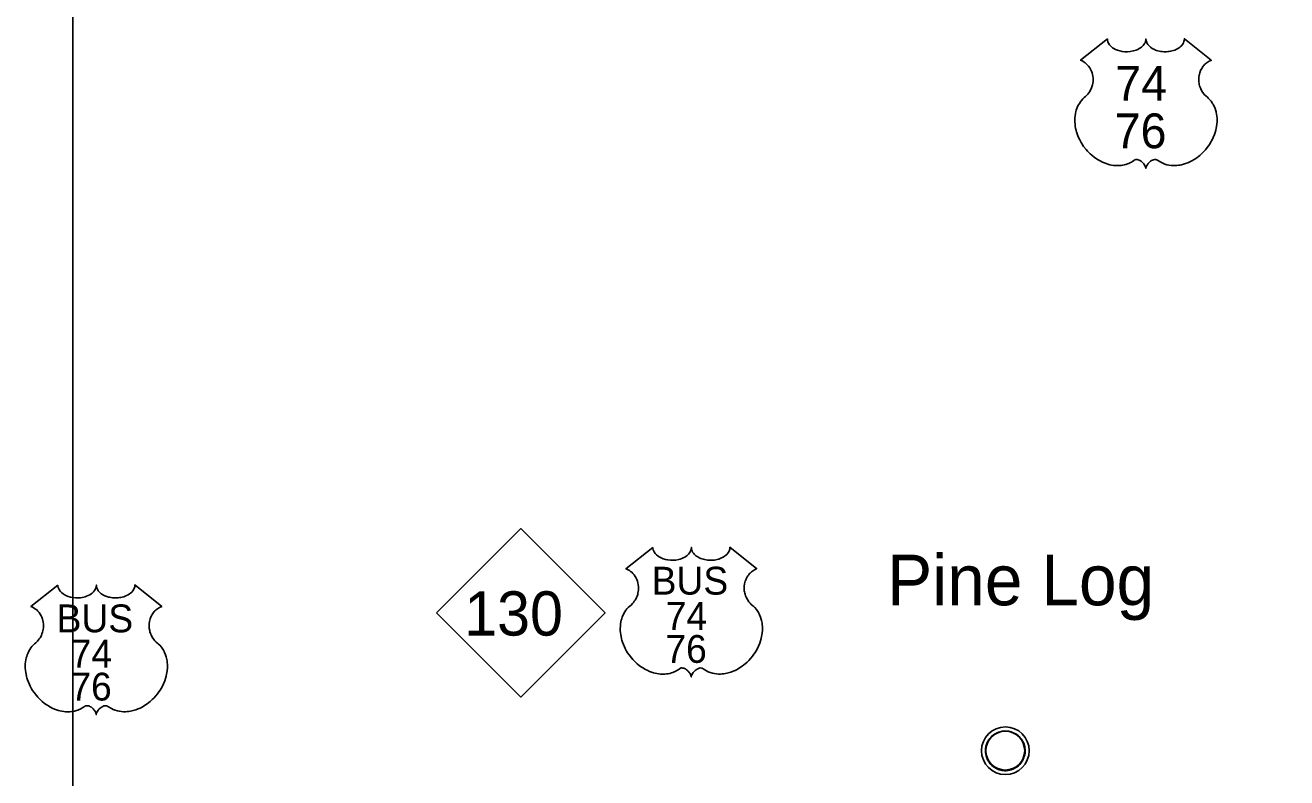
# Model space of a CAD drawing. Extents: x 5197761 to 5514561, y 1890130 to 2080942.
# Drawn here: x 5298153 to 5318095, y 2009899 to 2021798 of the extents above; entities that cross this region are included whole.
import ezdxf

# ---------------------------------------------------------------- set-up
doc = ezdxf.new("R2010")
doc.units = 0
for name, color, linetype in [('Exist Civil Demographics Community CELL', 7, 'Continuous'), ('Exist Civil Demographics Community Label', 7, 'Continuous'), ('Exist Road Primary NC Shield CELL', 7, 'Continuous'), ('Exist Road Primary NC Shield Number Label', 7, 'Continuous'), ('Exist Road Primary US Shield CELL', 7, 'Continuous'), ('Exist Road Primary US Shield Number Label', 7, 'Continuous'), ('Map Preparation Inset Cut Line', 7, 'Continuous')]:
    doc.layers.add(name, color=color, linetype=linetype)

msp = doc.modelspace()

# ---------------------------------------------------------------- linework, layer by layer
at = {"layer": 'Exist Civil Demographics Community CELL'}
msp.add_lwpolyline([(5313336, 2010377), (5313340, 2010399), (5313347, 2010426), (5313359, 2010454), (5313370, 2010477), (5313384, 2010500), (5313399, 2010521), (5313415, 2010538), (5313433, 2010557), (5313455, 2010575), (5313477, 2010590), (5313496, 2010601), (5313517, 2010611), (5313538, 2010620), (5313561, 2010627), (5313578, 2010632), (5313598, 2010635), (5313614, 2010638), (5313640, 2010639), (5313657, 2010638), (5313680, 2010637), (5313700, 2010635), (5313719, 2010631), (5313739, 2010625), (5313760, 2010617), (5313787, 2010606), (5313812, 2010592), (5313832, 2010577), (5313853, 2010561), (5313866, 2010549), (5313882, 2010531), (5313898, 2010512), (5313910, 2010494), (5313923, 2010474), (5313932, 2010453), (5313941, 2010433), (5313947, 2010413), (5313952, 2010395), (5313956, 2010371), (5313959, 2010352), (5313960, 2010328), (5313959, 2010305), (5313957, 2010282), (5313953, 2010260), (5313946, 2010235), (5313939, 2010212), (5313930, 2010192), (5313917, 2010168), (5313904, 2010147), (5313890, 2010128), (5313873, 2010109), (5313852, 2010089), (5313832, 2010072), (5313812, 2010059), (5313795, 2010049), (5313767, 2010036), (5313739, 2010025), (5313715, 2010019), (5313689, 2010014), (5313671, 2010012), (5313653, 2010011), (5313631, 2010011), (5313614, 2010013), (5313591, 2010015), (5313567, 2010021), (5313549, 2010026), (5313528, 2010033), (5313510, 2010041), (5313494, 2010050), (5313467, 2010067), (5313445, 2010084), (5313425, 2010102), (5313407, 2010121), (5313395, 2010137), (5313383, 2010154), (5313366, 2010182), (5313359, 2010196), (5313352, 2010212), (5313342, 2010245), (5313336, 2010273), (5313333, 2010294), (5313332, 2010319), (5313332, 2010338), (5313334, 2010364)], close=True, dxfattribs=at)
for centre, radius in [((5313646, 2010327), 377), ((5313645, 2010328), 307)]:
    msp.add_circle(centre, radius, dxfattribs=at)
at = {"layer": 'Exist Road Primary NC Shield CELL'}
msp.add_lwpolyline([(5304655, 2012506), (5305987, 2013838), (5307319, 2012506), (5305987, 2011174)], close=True, dxfattribs=at)
at = {"layer": 'Exist Road Primary US Shield CELL'}
for points in [[(5315260, 2021581), (5315261, 2021564), (5315265, 2021543), (5315268, 2021532), (5315278, 2021512), (5315294, 2021487), (5315317, 2021463), (5315342, 2021443), (5315359, 2021431), (5315388, 2021416), (5315421, 2021402), (5315458, 2021392), (5315495, 2021384), (5315536, 2021379), (5315577, 2021379), (5315620, 2021382), (5315668, 2021391), (5315691, 2021397), (5315716, 2021406), (5315739, 2021415), (5315764, 2021429), (5315784, 2021442), (5315800, 2021453), (5315823, 2021475), (5315841, 2021497), (5315848, 2021510), (5315855, 2021522), (5315864, 2021548), (5315866, 2021559), (5315868, 2021582), (5315870, 2021563), (5315872, 2021550), (5315875, 2021538), (5315880, 2021525), (5315889, 2021507), (5315899, 2021492), (5315918, 2021470), (5315930, 2021459), (5315941, 2021450), (5315969, 2021430), (5316003, 2021413), (5316020, 2021406), (5316037, 2021400), (5316058, 2021393), (5316081, 2021388), (5316103, 2021384), (5316125, 2021381), (5316149, 2021379), (5316167, 2021379), (5316191, 2021379), (5316212, 2021380), (5316234, 2021383), (5316258, 2021387), (5316277, 2021391), (5316303, 2021398), (5316326, 2021406), (5316346, 2021415), (5316373, 2021429), (5316394, 2021442), (5316409, 2021455), (5316428, 2021472), (5316446, 2021492), (5316456, 2021507), (5316463, 2021522), (5316470, 2021538), (5316474, 2021555), (5316476, 2021570), (5316477, 2021583), (5316902, 2021244), (5316892, 2021240), (5316869, 2021229), (5316850, 2021218), (5316821, 2021198), (5316808, 2021186), (5316796, 2021175), (5316784, 2021162), (5316774, 2021150), (5316762, 2021133), (5316751, 2021116), (5316740, 2021097), (5316732, 2021081), (5316719, 2021047), (5316713, 2021025), (5316709, 2021007), (5316704, 2020969), (5316702, 2020951), (5316702, 2020933), (5316703, 2020914), (5316705, 2020896), (5316708, 2020877), (5316711, 2020861), (5316717, 2020840), (5316724, 2020817), (5316734, 2020794), (5316753, 2020757), (5316778, 2020719), (5316796, 2020698), (5316813, 2020680), (5316840, 2020658), (5316854, 2020645), (5316870, 2020629), (5316897, 2020598), (5316908, 2020583), (5316918, 2020567), (5316929, 2020550), (5316939, 2020532), (5316947, 2020516), (5316962, 2020480), (5316972, 2020445), (5316977, 2020426), (5316985, 2020384), (5316988, 2020364), (5316992, 2020323), (5316992, 2020274), (5316988, 2020227), (5316979, 2020172), (5316972, 2020140), (5316961, 2020102), (5316950, 2020069), (5316931, 2020021), (5316913, 2019985), (5316891, 2019944), (5316876, 2019919), (5316858, 2019893), (5316835, 2019862), (5316809, 2019829), (5316778, 2019795), (5316753, 2019770), (5316720, 2019740), (5316699, 2019723), (5316671, 2019702), (5316632, 2019676), (5316593, 2019653), (5316560, 2019636), (5316531, 2019624), (5316493, 2019610), (5316431, 2019592), (5316408, 2019587), (5316381, 2019583), (5316355, 2019581), (5316331, 2019579), (5316297, 2019579), (5316265, 2019582), (5316233, 2019586), (5316201, 2019593), (5316167, 2019603), (5316136, 2019615), (5316105, 2019631), (5316053, 2019664), (5316037, 2019672), (5316029, 2019674), (5316009, 2019675), (5315990, 2019671), (5315970, 2019663), (5315958, 2019657), (5315942, 2019647), (5315930, 2019637), (5315916, 2019623), (5315906, 2019612), (5315898, 2019603), (5315883, 2019579), (5315878, 2019568), (5315873, 2019554), (5315868, 2019533), (5315861, 2019560), (5315853, 2019577), (5315844, 2019592), (5315835, 2019606), (5315820, 2019623), (5315807, 2019635), (5315791, 2019648), (5315773, 2019659), (5315760, 2019666), (5315747, 2019671), (5315732, 2019674), (5315719, 2019675), (5315709, 2019675), (5315695, 2019672), (5315676, 2019658), (5315657, 2019645), (5315638, 2019633), (5315614, 2019621), (5315597, 2019613), (5315576, 2019605), (5315552, 2019596), (5315526, 2019590), (5315499, 2019584), (5315475, 2019581), (5315450, 2019578), (5315427, 2019578), (5315403, 2019578), (5315381, 2019580), (5315355, 2019582), (5315323, 2019587), (5315296, 2019593), (5315268, 2019600), (5315239, 2019609), (5315209, 2019621), (5315170, 2019638), (5315143, 2019652), (5315101, 2019676), (5315051, 2019711), (5315013, 2019741), (5314986, 2019766), (5314945, 2019807), (5314922, 2019834), (5314884, 2019882), (5314861, 2019917), (5314845, 2019943), (5314823, 2019984), (5314810, 2020010), (5314794, 2020047), (5314781, 2020082), (5314771, 2020114), (5314765, 2020135), (5314757, 2020172), (5314752, 2020198), (5314748, 2020233), (5314745, 2020270), (5314744, 2020305), (5314745, 2020334), (5314749, 2020367), (5314754, 2020402), (5314761, 2020433), (5314767, 2020455), (5314776, 2020481), (5314788, 2020511), (5314802, 2020539), (5314816, 2020562), (5314832, 2020587), (5314849, 2020609), (5314871, 2020632), (5314893, 2020654), (5314914, 2020671), (5314939, 2020695), (5314951, 2020709), (5314967, 2020730), (5314979, 2020748), (5314989, 2020765), (5315002, 2020790), (5315010, 2020809), (5315019, 2020837), (5315024, 2020857), (5315029, 2020883), (5315033, 2020908), (5315034, 2020938), (5315033, 2020963), (5315030, 2020993), (5315024, 2021021), (5315018, 2021045), (5315007, 2021074), (5314997, 2021094), (5314981, 2021122), (5314963, 2021148), (5314944, 2021169), (5314926, 2021188), (5314907, 2021202), (5314890, 2021214), (5314869, 2021227), (5314848, 2021238), (5314835, 2021243)], [(5308074, 2013541), (5308075, 2013524), (5308080, 2013503), (5308083, 2013492), (5308093, 2013471), (5308109, 2013447), (5308131, 2013423), (5308157, 2013402), (5308174, 2013391), (5308203, 2013376), (5308236, 2013362), (5308272, 2013351), (5308310, 2013344), (5308351, 2013339), (5308391, 2013338), (5308435, 2013342), (5308483, 2013351), (5308505, 2013357), (5308530, 2013365), (5308553, 2013375), (5308579, 2013388), (5308599, 2013402), (5308615, 2013413), (5308637, 2013435), (5308655, 2013457), (5308663, 2013470), (5308669, 2013482), (5308678, 2013507), (5308681, 2013519), (5308683, 2013542), (5308684, 2013522), (5308686, 2013510), (5308689, 2013498), (5308694, 2013485), (5308703, 2013467), (5308714, 2013452), (5308732, 2013430), (5308744, 2013419), (5308755, 2013410), (5308784, 2013390), (5308818, 2013373), (5308834, 2013366), (5308851, 2013360), (5308873, 2013353), (5308895, 2013348), (5308917, 2013344), (5308940, 2013341), (5308963, 2013339), (5308982, 2013338), (5309005, 2013339), (5309026, 2013340), (5309048, 2013342), (5309072, 2013346), (5309092, 2013351), (5309117, 2013358), (5309140, 2013366), (5309161, 2013375), (5309187, 2013388), (5309208, 2013402), (5309224, 2013414), (5309243, 2013431), (5309260, 2013452), (5309270, 2013467), (5309278, 2013482), (5309284, 2013498), (5309289, 2013515), (5309291, 2013530), (5309291, 2013543), (5309716, 2013204), (5309706, 2013200), (5309683, 2013189), (5309665, 2013178), (5309635, 2013157), (5309623, 2013146), (5309610, 2013134), (5309599, 2013122), (5309589, 2013110), (5309576, 2013093), (5309565, 2013076), (5309554, 2013057), (5309547, 2013041), (5309534, 2013006), (5309527, 2012985), (5309523, 2012966), (5309518, 2012928), (5309517, 2012910), (5309517, 2012893), (5309518, 2012874), (5309520, 2012856), (5309523, 2012837), (5309526, 2012820), (5309531, 2012800), (5309539, 2012776), (5309548, 2012753), (5309568, 2012716), (5309593, 2012679), (5309610, 2012658), (5309628, 2012640), (5309654, 2012618), (5309668, 2012605), (5309685, 2012589), (5309711, 2012558), (5309722, 2012543), (5309733, 2012527), (5309743, 2012510), (5309753, 2012492), (5309761, 2012476), (5309776, 2012440), (5309787, 2012404), (5309792, 2012386), (5309800, 2012344), (5309803, 2012323), (5309806, 2012283), (5309806, 2012233), (5309803, 2012187), (5309794, 2012132), (5309786, 2012100), (5309775, 2012062), (5309764, 2012029), (5309745, 2011980), (5309728, 2011945), (5309706, 2011904), (5309690, 2011879), (5309672, 2011852), (5309650, 2011822), (5309624, 2011789), (5309593, 2011755), (5309567, 2011729), (5309534, 2011700), (5309514, 2011683), (5309485, 2011661), (5309446, 2011635), (5309407, 2011613), (5309375, 2011596), (5309345, 2011584), (5309308, 2011569), (5309245, 2011552), (5309222, 2011547), (5309195, 2011543), (5309170, 2011541), (5309145, 2011539), (5309112, 2011539), (5309079, 2011542), (5309048, 2011546), (5309016, 2011553), (5308982, 2011563), (5308951, 2011575), (5308920, 2011590), (5308867, 2011624), (5308852, 2011632), (5308843, 2011634), (5308823, 2011635), (5308804, 2011631), (5308784, 2011623), (5308773, 2011617), (5308757, 2011606), (5308745, 2011597), (5308730, 2011583), (5308720, 2011572), (5308713, 2011562), (5308698, 2011539), (5308693, 2011528), (5308687, 2011514), (5308682, 2011493), (5308676, 2011519), (5308668, 2011537), (5308659, 2011552), (5308649, 2011565), (5308634, 2011582), (5308621, 2011595), (5308605, 2011608), (5308588, 2011619), (5308574, 2011626), (5308562, 2011630), (5308546, 2011634), (5308534, 2011635), (5308524, 2011635), (5308509, 2011632), (5308490, 2011618), (5308472, 2011605), (5308452, 2011593), (5308429, 2011580), (5308411, 2011572), (5308391, 2011564), (5308367, 2011556), (5308340, 2011549), (5308314, 2011544), (5308290, 2011540), (5308265, 2011538), (5308242, 2011537), (5308218, 2011538), (5308196, 2011539), (5308170, 2011542), (5308138, 2011546), (5308111, 2011552), (5308083, 2011560), (5308054, 2011569), (5308023, 2011581), (5307984, 2011598), (5307958, 2011611), (5307915, 2011636), (5307865, 2011670), (5307828, 2011701), (5307800, 2011726), (5307760, 2011767), (5307736, 2011794), (5307699, 2011842), (5307675, 2011877), (5307660, 2011902), (5307637, 2011944), (5307625, 2011969), (5307609, 2012007), (5307596, 2012042), (5307585, 2012074), (5307580, 2012095), (5307572, 2012131), (5307567, 2012157), (5307562, 2012193), (5307559, 2012230), (5307559, 2012265), (5307560, 2012293), (5307563, 2012327), (5307569, 2012362), (5307575, 2012392), (5307582, 2012414), (5307591, 2012441), (5307603, 2012470), (5307617, 2012498), (5307630, 2012522), (5307647, 2012547), (5307663, 2012568), (5307685, 2012592), (5307708, 2012613), (5307729, 2012630), (5307753, 2012654), (5307766, 2012669), (5307781, 2012689), (5307794, 2012708), (5307803, 2012725), (5307816, 2012750), (5307824, 2012768), (5307834, 2012797), (5307839, 2012817), (5307844, 2012843), (5307847, 2012867), (5307848, 2012898), (5307848, 2012923), (5307844, 2012952), (5307839, 2012980), (5307832, 2013005), (5307822, 2013033), (5307812, 2013054), (5307796, 2013082), (5307778, 2013108), (5307759, 2013129), (5307740, 2013148), (5307722, 2013162), (5307705, 2013174), (5307683, 2013187), (5307662, 2013197), (5307649, 2013203)], [(5298668, 2012946), (5298669, 2012928), (5298674, 2012907), (5298677, 2012896), (5298687, 2012876), (5298703, 2012851), (5298725, 2012828), (5298751, 2012807), (5298768, 2012796), (5298797, 2012780), (5298830, 2012766), (5298866, 2012756), (5298904, 2012748), (5298945, 2012744), (5298985, 2012743), (5299029, 2012746), (5299077, 2012755), (5299099, 2012761), (5299124, 2012770), (5299147, 2012779), (5299173, 2012793), (5299193, 2012806), (5299209, 2012817), (5299231, 2012839), (5299249, 2012861), (5299257, 2012874), (5299264, 2012886), (5299272, 2012912), (5299275, 2012923), (5299277, 2012946), (5299278, 2012927), (5299280, 2012914), (5299283, 2012902), (5299288, 2012890), (5299298, 2012871), (5299308, 2012856), (5299327, 2012834), (5299338, 2012823), (5299349, 2012814), (5299378, 2012794), (5299412, 2012777), (5299428, 2012770), (5299445, 2012764), (5299467, 2012757), (5299489, 2012752), (5299511, 2012748), (5299534, 2012745), (5299557, 2012743), (5299576, 2012743), (5299599, 2012743), (5299620, 2012744), (5299642, 2012747), (5299666, 2012751), (5299686, 2012755), (5299711, 2012762), (5299734, 2012770), (5299755, 2012779), (5299781, 2012793), (5299802, 2012806), (5299818, 2012819), (5299837, 2012836), (5299854, 2012856), (5299864, 2012871), (5299872, 2012886), (5299879, 2012902), (5299883, 2012919), (5299885, 2012934), (5299885, 2012947), (5300310, 2012608), (5300300, 2012604), (5300277, 2012593), (5300259, 2012582), (5300229, 2012562), (5300217, 2012550), (5300204, 2012539), (5300193, 2012526), (5300183, 2012514), (5300170, 2012497), (5300159, 2012480), (5300149, 2012461), (5300141, 2012445), (5300128, 2012411), (5300121, 2012389), (5300117, 2012371), (5300112, 2012333), (5300111, 2012315), (5300111, 2012297), (5300112, 2012278), (5300114, 2012260), (5300117, 2012241), (5300120, 2012225), (5300125, 2012204), (5300133, 2012181), (5300142, 2012158), (5300162, 2012121), (5300187, 2012083), (5300204, 2012062), (5300222, 2012044), (5300248, 2012022), (5300262, 2012009), (5300279, 2011993), (5300305, 2011962), (5300316, 2011948), (5300327, 2011931), (5300337, 2011914), (5300347, 2011896), (5300355, 2011880), (5300370, 2011844), (5300381, 2011809), (5300386, 2011790), (5300394, 2011748), (5300397, 2011728), (5300400, 2011687), (5300400, 2011638), (5300397, 2011591), (5300388, 2011537), (5300380, 2011504), (5300369, 2011466), (5300359, 2011433), (5300339, 2011385), (5300322, 2011349), (5300300, 2011308), (5300284, 2011283), (5300266, 2011257), (5300244, 2011226), (5300218, 2011193), (5300187, 2011159), (5300161, 2011134), (5300128, 2011104), (5300108, 2011087), (5300079, 2011066), (5300040, 2011040), (5300002, 2011017), (5299969, 2011001), (5299940, 2010988), (5299902, 2010974), (5299839, 2010956), (5299816, 2010952), (5299789, 2010948), (5299764, 2010945), (5299739, 2010944), (5299706, 2010944), (5299673, 2010946), (5299642, 2010951), (5299610, 2010957), (5299576, 2010967), (5299545, 2010979), (5299514, 2010995), (5299461, 2011028), (5299446, 2011036), (5299438, 2011038), (5299417, 2011039), (5299398, 2011035), (5299379, 2011027), (5299367, 2011021), (5299351, 2011011), (5299339, 2011001), (5299324, 2010987), (5299314, 2010976), (5299307, 2010967), (5299292, 2010944), (5299287, 2010932), (5299281, 2010918), (5299276, 2010897), (5299270, 2010924), (5299262, 2010941), (5299253, 2010956), (5299243, 2010970), (5299228, 2010987), (5299215, 2011000), (5299199, 2011013), (5299182, 2011023), (5299168, 2011030), (5299156, 2011035), (5299140, 2011038), (5299128, 2011039), (5299118, 2011039), (5299103, 2011036), (5299084, 2011022), (5299066, 2011010), (5299046, 2010997), (5299023, 2010985), (5299005, 2010977), (5298985, 2010969), (5298961, 2010961), (5298934, 2010954), (5298908, 2010949), (5298884, 2010945), (5298859, 2010943), (5298836, 2010942), (5298812, 2010942), (5298790, 2010944), (5298764, 2010946), (5298732, 2010951), (5298705, 2010957), (5298677, 2010964), (5298648, 2010973), (5298617, 2010985), (5298578, 2011002), (5298552, 2011016), (5298509, 2011040), (5298459, 2011075), (5298422, 2011105), (5298394, 2011130), (5298354, 2011171), (5298330, 2011198), (5298293, 2011246), (5298269, 2011281), (5298254, 2011307), (5298231, 2011348), (5298219, 2011374), (5298203, 2011411), (5298190, 2011446), (5298179, 2011479), (5298174, 2011499), (5298166, 2011536), (5298161, 2011562), (5298156, 2011597), (5298153, 2011635), (5298153, 2011669), (5298154, 2011698), (5298157, 2011731), (5298163, 2011766), (5298170, 2011797), (5298176, 2011819), (5298185, 2011845), (5298197, 2011875), (5298211, 2011903), (5298224, 2011926), (5298241, 2011951), (5298258, 2011973), (5298279, 2011996), (5298302, 2012018), (5298323, 2012035), (5298347, 2012059), (5298360, 2012073), (5298375, 2012094), (5298388, 2012113), (5298397, 2012129), (5298410, 2012154), (5298418, 2012173), (5298428, 2012202), (5298433, 2012222), (5298438, 2012247), (5298441, 2012272), (5298442, 2012302), (5298442, 2012327), (5298438, 2012357), (5298433, 2012385), (5298426, 2012409), (5298416, 2012438), (5298406, 2012458), (5298390, 2012486), (5298372, 2012512), (5298353, 2012533), (5298334, 2012552), (5298316, 2012566), (5298299, 2012578), (5298277, 2012591), (5298256, 2012602), (5298243, 2012607)]]:
    msp.add_lwpolyline(points, close=True, dxfattribs=at)
at = {"layer": 'Map Preparation Inset Cut Line'}
msp.add_lwpolyline([(5337121, 2027499), (5337121, 2030497), (5298905, 2030497), (5298905, 1990962), (5337121, 1990962), (5337121, 1992535)], dxfattribs=at)

# ---------------------------------------------------------------- texts
at = {"layer": 'Exist Civil Demographics Community Label'}
msp.add_text('Pine Log', height=800, dxfattribs=at).set_placement((5311776, 2012626))
at = {"layer": 'Exist Road Primary NC Shield Number Label'}
msp.add_text('130', height=700, dxfattribs=at).set_placement((5305091, 2012147))
at = {"layer": 'Exist Road Primary US Shield Number Label'}
for s, height, p in [('74', 550, (5315384, 2020605)), ('76', 550, (5315375, 2019853)), ('BUS', 440, (5308055, 2012795)), ('BUS', 440, (5298649, 2012199)), ('74', 440, (5308277, 2012238)), ('76', 440, (5308272, 2011716)), ('74', 440, (5298871, 2011642)), ('76', 440, (5298866, 2011120))]:
    msp.add_text(s, height=height, dxfattribs=at).set_placement(p)

doc.saveas('drawing.dxf')
